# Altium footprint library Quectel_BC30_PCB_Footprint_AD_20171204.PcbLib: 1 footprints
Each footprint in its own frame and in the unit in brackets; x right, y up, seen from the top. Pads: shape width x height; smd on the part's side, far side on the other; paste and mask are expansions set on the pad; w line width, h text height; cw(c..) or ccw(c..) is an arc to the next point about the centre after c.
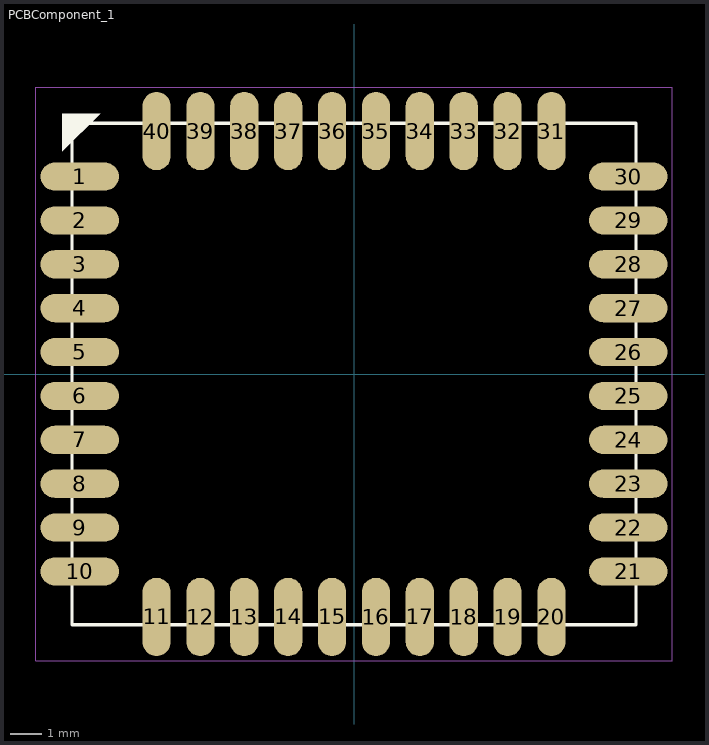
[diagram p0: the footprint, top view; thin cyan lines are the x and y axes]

## PCBComponent_1 [mm]
pads (40):
  oval 2.5x0.9 smd mask+0.05: 1(-8.75,6.3) 2(-8.75,4.9) 3(-8.75,3.5) 4(-8.75,2.1) 5(-8.75,0.7) 6(-8.75,-0.7) 7(-8.75,-2.1) 8(-8.75,-3.5) 9(-8.75,-4.9) 10(-8.75,-6.3) 21(8.75,-6.3) 22(8.75,-4.9) 23(8.75,-3.5) 24(8.75,-2.1) 25(8.75,-0.7) 26(8.75,0.7) 27(8.75,2.1) 28(8.75,3.5) 29(8.75,4.9) 30(8.75,6.3)
  oval 0.9x2.5 smd mask+0.05: 11(-6.3,-7.75) 12(-4.9,-7.75) 13(-3.5,-7.75) 14(-2.1,-7.75) 15(-0.7,-7.75) 16(0.7,-7.75) 17(2.1,-7.75) 18(3.5,-7.75) 19(4.9,-7.75) 20(6.3,-7.75) 31(6.3,7.75) 32(4.9,7.75) 33(3.5,7.75) 34(2.1,7.75) 35(0.7,7.75) 36(-0.7,7.75) 37(-2.1,7.75) 38(-3.5,7.75) 39(-4.9,7.75) 40(-6.3,7.75)
Top Overlay:
  region: -8.1,8.3 -9.3,8.3 -9.3,7.1
  lines w0.1: -9,-8 9,-8 9,8 -9,8 -9,-8
Mechanical 1:
  lines w0.01: -10.15,-9.15 10.15,-9.15 10.15,9.15 -10.15,9.15 -10.15,-9.15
